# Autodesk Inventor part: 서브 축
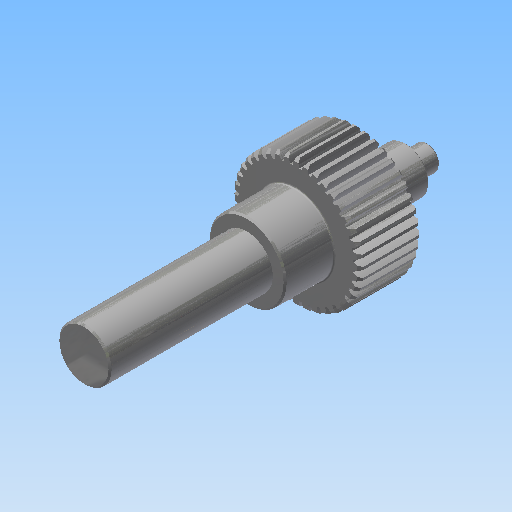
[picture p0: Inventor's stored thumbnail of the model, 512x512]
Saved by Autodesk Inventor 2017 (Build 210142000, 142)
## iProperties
Created: 2016-02
Part Number: 서브 축
Material: 강철, 연강
Document SubType Name: Modeling
Designer: mdu
Categories: <?xml version="1.0" encoding="UTF-16"?> <MemberInstance><Categories><FamilyTemplate><FamilyTemplateParameter ValueType="xs:double" Id="1" ObjectReferenceKey="da
Density: 7.86 g/cm^3
Appearance: 강철
CustomPartVersion: 1
Author: mdu
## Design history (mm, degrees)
sketch "Sketch1"
  geometry: C1 r 21 at (0, 0)
  constraints: 1 centre point
  dimensions: "d0" = 42 diameter of C1 (= da_da)
extrude "Extrusion1" new body sketch "Sketch1" distance "d1" = 20 (= da_b); taper "d2" = 0 deg
workplane "Work Plane2"
feature "피치 지름" dims "d4" = 10, "d5" = 0
workplane "Work Plane8"
workplane "Work Plane9"
chamfer "모따기1" distance "d49" = 1; stored, may be unused: second distance "d50" = 2, angle "d51" = 45 deg
sketch "스케치3"
  geometry: C1 r 12.5 at (0, 0); 1 further point
  constraints: 1 centre point, 1 coincident
  dimensions: "d52" = 25 diameter of C1
extrude "돌출2" join sketch "스케치3" distance "d53" = 16; taper "d54" = 0 deg
sketch "스케치4"
  geometry: C1 r 8.5 at (0, 0); 1 further point
  constraints: 1 centre point, 1 coincident
  dimensions: "d55" = 17 diameter of C1
extrude "돌출3" join sketch "스케치4" distance "d56" = 53; taper "d57" = 0 deg
sketch "스케치5"
  geometry: C1 r 7.5 at (0, 0); 1 further point
  constraints: 1 centre point, 1 coincident
  dimensions: "d62" = 15 diameter of C1
extrude "돌출4" join sketch "스케치5" distance "d63" = 16; taper "d64" = 0 deg
sketch "스케치6"
  geometry: C1 r 4 at (0, 0); 1 further point
  constraints: 1 centre point, 1 coincident
  dimensions: "d65" = 8 diameter of C1
extrude "돌출5" join sketch "스케치6" distance "d66" = 7; taper "d67" = 0 deg
chamfer "모따기2" distance "d58" = 0.5; stored, may be unused: second distance "d59" = 2, angle "d60" = 45 deg
fillet "모깎기1" dims "d61" = 0.5
feature "스퍼 기어" dims "d34" = 4.5 deg (computed from da_z), "da_b" = 20, "da_d" = 40, "da_aw" = 31, "da_da" = 42, "da_df" = 37.5, "da_dw" = 40, angle "da_beta" = 0 deg, "da_lefttooth" = 0, "da_righttooth" = 0
body "Solid1"
sketch "Sketch2"
  geometry: C1 r 21 at (0, 0) reference; C2 r 20 at (0, 0)
  constraints: 1 centre point, 1 coincident
  dimensions: "d3" = 40 diameter of C2 (= da_dw)
body "Srf1"
other parameters: "d16" = 31 (= da_aw), "d17" = 0, "d39" = 0, "d41" = 0, "d43" = 31 (= da_aw), "d46" = 31 (= da_aw), "d47" = 0, "d48" = 0
